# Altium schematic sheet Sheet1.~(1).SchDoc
size A; SheetNumber: 1; SheetTotal: 1
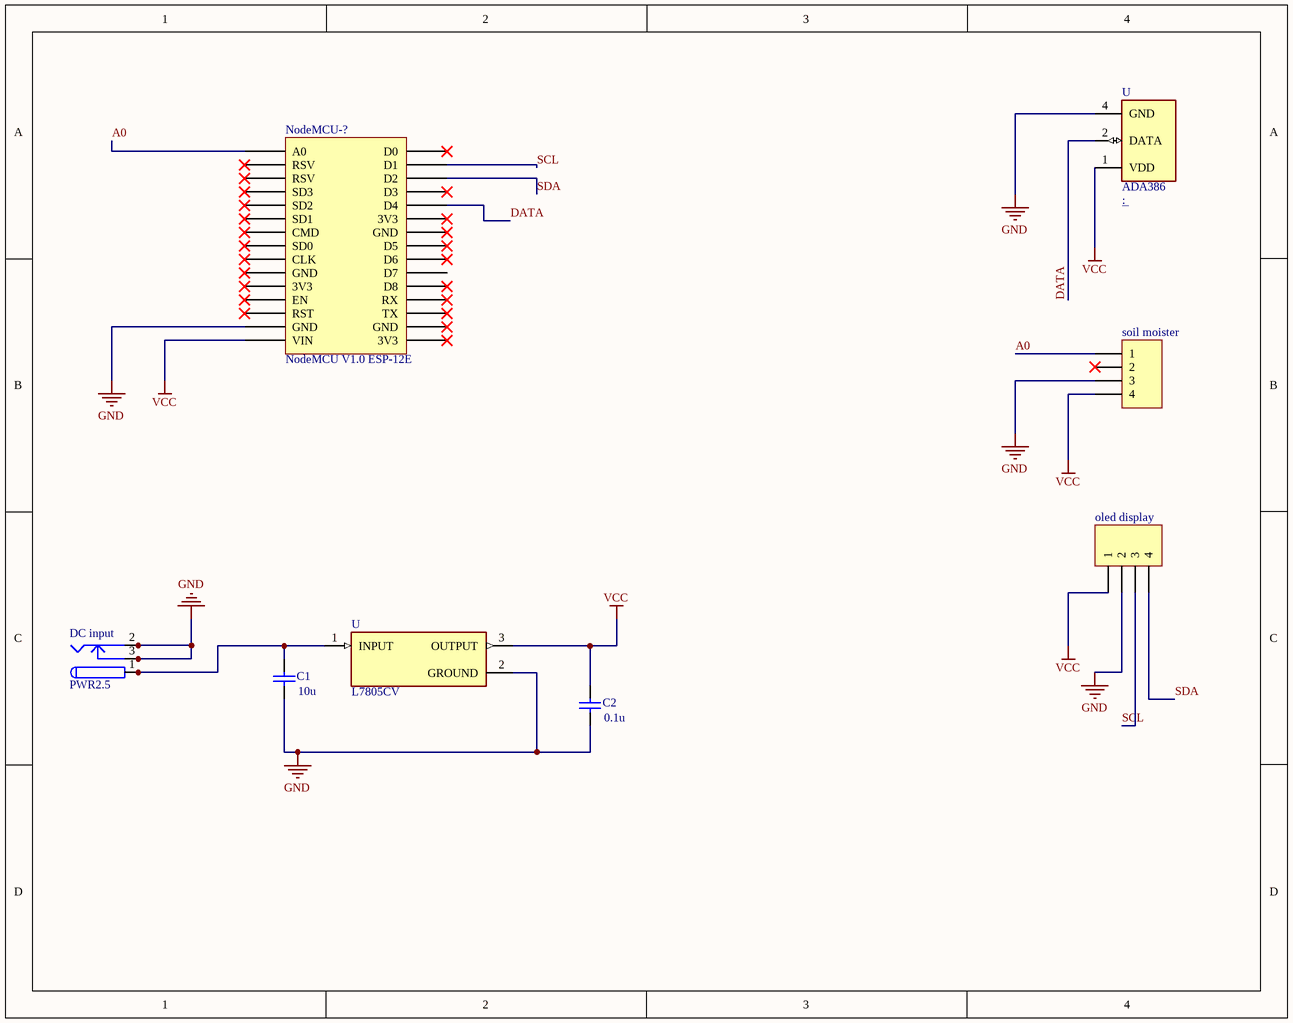
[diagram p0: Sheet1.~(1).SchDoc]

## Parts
(Parts that share a designator on the sheet are numbered #1, #2 ... from top to bottom, then left to right.)
C1  value 10u  [C1206]
C2  value 0.1u  [C1206]
DC_input  PWR2.5  [KLD-0202]
NodeMCU-?  NodeMCU V1.0 ESP-12E  [NodeMCU V1.0 ESP-12E]
oled_display  (no value)  [HDR1X4]
soil_moister  (no value)  [HDR1X4]
U#1  ADA386  [XDCR_ADA386]
U#2  L7805CV  [TO255P1040X460X1968-3]

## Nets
GND: C1.1 C2.1 DC_input.2 DC_input.2A DC_input.2B DC_input.3 DC_input.3A DC_input.3B NodeMCU-?.GND oled_display.2 soil_moister.3 U#1.4(GND) U#2.2(GROUND)
VCC: C2.2 NodeMCU-?.VIN oled_display.1 soil_moister.4 U#1.1(VDD) U#2.3(OUTPUT)
A0: NodeMCU-?.A0 soil_moister.1
DATA: NodeMCU-?.D4 U#1.2(DATA)
SCL: NodeMCU-?.D1 oled_display.3
SDA: NodeMCU-?.D2 oled_display.4
NetC1_2: C1.2 DC_input.1 DC_input.1A DC_input.1B U#2.1(INPUT)

Not connected (* = marked no-connect by the designer): NodeMCU-? 3V3* CLK* CMD* D0* D3* D5* D6* D7 D8* EN* RST* RSV* RX* SD0* SD1* SD2* SD3* TX*; soil_moister 2*

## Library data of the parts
C1 C2 = Cap Semi: Capacitor (Semiconductor SIM Model)
DC_input = PWR2.5: Low Voltage Power Supply Connector
NodeMCU-? = NodeMCU V1.0 ESP-12E: NodeMCU V1.0 ESP8266 (ESP-12E)
oled_display = Header 4
soil_moister = Header 4: soil moister pin header
U#1 = ADA386: MF: Adafruit Industries
U#2 = L7805CV: Linear Voltage Regulator IC 1 Output 1.5A TO-220AB; MF: STMicroelectronics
